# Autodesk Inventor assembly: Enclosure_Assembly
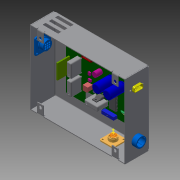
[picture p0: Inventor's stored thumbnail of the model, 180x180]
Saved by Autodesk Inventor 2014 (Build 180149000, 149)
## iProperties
Shininess: 64.0
Length Units: 11272
Angle Units: 11279
Time Units: 11290
Mass Units: 11286
Length Display Precision: 3
Angle Display Precision: 2
Compacted: True
Part Number: Enclosure_Assembly
Document SubType Name: Assembly
Created: 2003-08
Designer: t_enrig
Manufacturer: Standard
Standards Organization: Custom
Mass: 170.709 g
Surface Area: 1869.73 cm^2
Volume: 170.709 cm^3
Density: 1 g/cm^3
Density: 0.0
Volumn: 0.0
Area: 0.0
PropertySet Name: Model Information
Control State: 0
Master: False
Checked Out: False
Author: t_enrig
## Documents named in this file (6)
- C:\Users\iTools\Desktop\tutorial files\Cable and Harness\Enclosure_Assembly.iam
- C:\Users\iTools\Desktop\tutorial files\Cable and Harness\Enclosure.ipt
- C:\Users\iTools\Desktop\tutorial files\Cable and Harness\PCB.iam
- C:\Users\iTools\Desktop\tutorial files\Cable and Harness\360124.ipt
- C:\Users\iTools\Desktop\tutorial files\Cable and Harness\360575.ipt
- C:\Users\iTools\Desktop\tutorial files\Cable and Harness\Enclosure_Assembly\AIP\Cable and Harness\Ribbon Cable.iam
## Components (6 placed, 5 different names)
1. Enclosure:1 — Mate:1, Mate:2, Mate:3, Insert:1, Insert:2, Insert:3, Angle:1, Mate:4, Mate:5, Mate:6
2. PCB:1 [sub-assembly] — Mate:1, Mate:2, Mate:3
3. 360124:1 — Insert:2
4. 360575:1 — Insert:1
5. 360575:2 — Insert:3, Angle:1
6. Ribbon Cable [sub-assembly] — Mate:4, Mate:5, Mate:6
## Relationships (10: Mate 6, Insert 3, Angle 1)
- Mate:1: Enclosure:1 ↔ PCB:1
- Mate:2: Enclosure:1 ↔ PCB:1
- Mate:3: Enclosure:1 ↔ PCB:1
- Insert:1: Enclosure:1 ↔ 360575:1
- Insert:2: Enclosure:1 ↔ 360124:1
- Insert:3: Enclosure:1 ↔ 360575:2
- Angle:1: Enclosure:1 ↔ 360575:2
- Mate:4: Enclosure:1 ↔ Ribbon Cable
- Mate:5: Enclosure:1 ↔ Ribbon Cable
- Mate:6: Enclosure:1 ↔ Ribbon Cable
